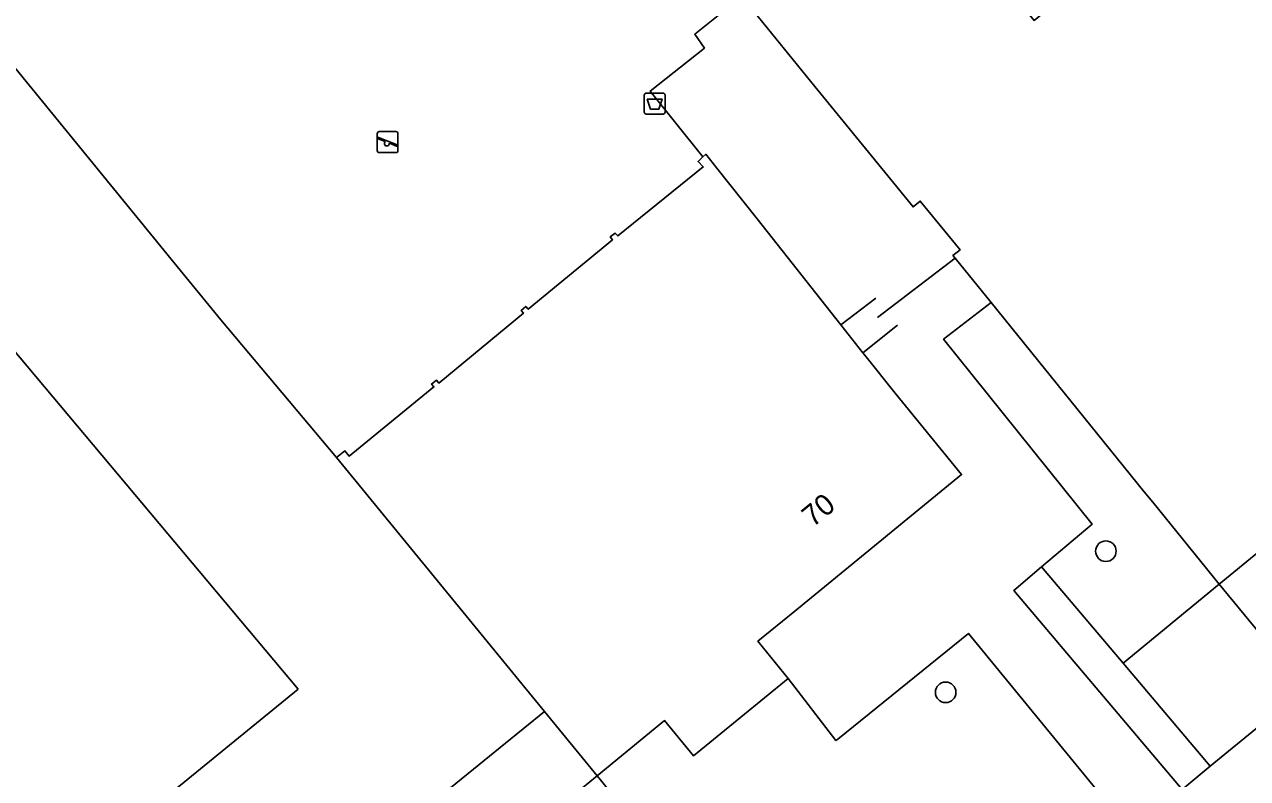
# Model space of a CAD drawing. Extents: x 162074 to 163034, y 381824 to 382557.
# Drawn here: x 162552.1 to 162610.3, y 381921.2 to 381957.1 of the extents above; entities that cross this region are included whole.
import ezdxf

# ---------------------------------------------------------------- set-up
doc = ezdxf.new("R2010")
doc.units = 0
for name, color, linetype in [('IMGEO_Afvalbak', 7, 'Continuous'), ('IMGEO_Boom', 7, 'Continuous'), ('IMGEO_Groenvoorziening', 7, 'Continuous'), ('IMGEO_Hek', 7, 'Continuous'), ('IMGEO_Pand', 7, 'Continuous'), ('IMGEO_Pand_nummerreeks', 7, 'Continuous'), ('IMGEO_Rijbaan_lokaal_open', 7, 'Continuous'), ('IMGEO_Rijbaan_regionaal_gesloten', 7, 'Continuous'), ('IMGEO_Speelvoorziening', 7, 'Continuous'), ('IMGEO_Voetpad_open', 7, 'Continuous')]:
    doc.layers.add(name, color=color, linetype=linetype)

msp = doc.modelspace()

# ---------------------------------------------------------------- linework, layer by layer
at = {"layer": 'IMGEO_Afvalbak'}
for p, q in [((162581.607, 381952.905), (162581.607, 381953.705)), ((162581.607, 381953.705), (162581.607, 381952.905)), ((162581.707, 381953.805), (162582.497, 381953.805)), ((162582.497, 381953.805), (162581.707, 381953.805)), ((162582.597, 381953.705), (162582.597, 381952.905)), ((162582.597, 381952.905), (162582.597, 381953.705)), ((162582.497, 381952.805), (162581.707, 381952.805)), ((162581.707, 381952.805), (162582.497, 381952.805))]:
    msp.add_line(p, q, dxfattribs=at)
msp.add_lwpolyline([(162581.75, 381953.519), (162582.454, 381953.519), (162582.305, 381953.049), (162581.899, 381953.049), (162581.75, 381953.519)], dxfattribs=at)
for centre, start, end in [((162581.707, 381953.705), 90, 180), ((162581.707, 381953.705), 90, 180), ((162582.497, 381953.705), 0, 90), ((162582.497, 381953.705), 360, 90), ((162581.707, 381952.905), 180, 270), ((162581.707, 381952.905), 180, 270), ((162582.497, 381952.905), 270, 0), ((162582.497, 381952.905), 270, 0)]:
    msp.add_arc(centre, 0.1, start, end, dxfattribs=at)
at = {"layer": 'IMGEO_Boom'}
for centre in [(162603.558, 381932.03), (162595.937, 381925.32)]:
    msp.add_circle(centre, 0.489, dxfattribs=at)
at = {"layer": 'IMGEO_Groenvoorziening'}
for points in [[(162604.374, 381926.708), (162600.502, 381931.282)], [(162608.939, 381930.467), (162604.374, 381926.708)], [(162608.939, 381930.467), (162613.031, 381925.508)], [(162608.52, 381921.81), (162604.374, 381926.708)], [(162579.358, 381921.35), (162583.171, 381916.7), (162590.856, 381907.327)]]:
    msp.add_lwpolyline(points, dxfattribs=at)
at = {"layer": 'IMGEO_Hek'}
for points in [[(162592.7, 381943.146), (162596.393, 381945.952)], [(162590.953, 381942.794), (162592.612, 381944.061)], [(162592.007, 381941.465), (162593.649, 381942.77)]]:
    msp.add_lwpolyline(points, dxfattribs=at)
at = {"layer": 'IMGEO_Pand'}
for points in [[(162580.989, 381965.07), (162582.996, 381966.707), (162590.131, 381957.956), (162595.778, 381962.577), (162600.14, 381957.261), (162625.783, 381978.273), (162640.017, 381960.503), (162633.898, 381955.497), (162633.564, 381955.907), (162630.873, 381953.706), (162633.469, 381950.533), (162608.939, 381930.467)], [(162598.107, 381943.844), (162596.393, 381945.952), (162596.286, 381946.083), (162596.627, 381946.361), (162594.733, 381948.676), (162594.392, 381948.398), (162589.722, 381954.124), (162586.627, 381957.92), (162581.57, 381964.121), (162580.873, 381964.976), (162580.989, 381965.07)], [(162548.165, 381953.339), (162551.085, 381955.732), (162551.227, 381955.558), (162559.253, 381945.742), (162561.474, 381943.025), (162566.975, 381936.477)], [(162566.975, 381936.477), (162567.37, 381936.798), (162567.572, 381936.549), (162571.599, 381939.84), (162571.491, 381939.972), (162571.725, 381940.162), (162571.838, 381940.019), (162575.86, 381943.339), (162575.746, 381943.465), (162575.969, 381943.667), (162576.085, 381943.534), (162580.093, 381946.834), (162579.987, 381946.967), (162580.22, 381947.152), (162580.344, 381947.013), (162584.407, 381950.296), (162584.167, 381950.55), (162584.397, 381950.771)], [(162584.397, 381950.771), (162584.532, 381950.895), (162585.058, 381950.231), (162586.967, 381947.822), (162590.953, 381942.794), (162592.007, 381941.465), (162592.161, 381941.27), (162593.53, 381939.543), (162596.696, 381935.673), (162588.759, 381929.179), (162587.009, 381927.748), (162588.456, 381925.978)], [(162598.107, 381943.844), (162605.386, 381934.855), (162605.792, 381934.353), (162608.939, 381930.467)], [(162565.141, 381925.467), (162548.187, 381911.662), (162535.815, 381926.855), (162551.463, 381939.598), (162550.445, 381940.847), (162551.517, 381941.719), (162565.141, 381925.467)], [(162576.856, 381924.407), (162566.975, 381936.477)], [(162588.456, 381925.978), (162583.953, 381922.295), (162582.574, 381923.981), (162579.358, 381921.35)], [(162574.906, 381913.476), (162571.749, 381917.353), (162570.041, 381919.451), (162571.599, 381920.72), (162571.89, 381920.363), (162576.856, 381924.407)], [(162576.856, 381924.407), (162579.358, 381921.35)]]:
    msp.add_lwpolyline(points, dxfattribs=at)
at = {"layer": 'IMGEO_Rijbaan_lokaal_open'}
msp.add_lwpolyline([(162579.358, 381921.35), (162578.487, 381920.638)], dxfattribs=at)
at = {"layer": 'IMGEO_Rijbaan_regionaal_gesloten'}
msp.add_arc((167033.423, 376567.715), 6927.186, 129.0651232, 129.6890786, dxfattribs=at)
at = {"layer": 'IMGEO_Speelvoorziening'}
for p, q in [((162568.904, 381951.074), (162568.904, 381951.874)), ((162568.904, 381951.874), (162568.904, 381951.074)), ((162569.004, 381951.974), (162569.794, 381951.974)), ((162569.794, 381951.974), (162569.004, 381951.974)), ((162569.894, 381951.874), (162569.894, 381951.074)), ((162569.894, 381951.074), (162569.894, 381951.874)), ((162569.287, 381951.502), (162568.948, 381951.639)), ((162568.973, 381951.699), (162569.849, 381951.346)), ((162569.825, 381951.286), (162569.485, 381951.423)), ((162569.794, 381950.974), (162569.004, 381950.974)), ((162569.004, 381950.974), (162569.794, 381950.974))]:
    msp.add_line(p, q, dxfattribs=at)
for centre, radius, start, end in [((162569.004, 381951.874), 0.1, 90, 180), ((162569.004, 381951.874), 0.1, 90, 180), ((162569.794, 381951.874), 0.1, 0, 90), ((162569.794, 381951.874), 0.1, 360, 90), ((162568.961, 381951.669), 0.0327, 68.07798, 248.07798), ((162569.366, 381951.412), 0.12, 130.99278, 5.16318), ((162569.837, 381951.316), 0.0327, 248.07798, 68.07798), ((162569.004, 381951.074), 0.1, 180, 270), ((162569.004, 381951.074), 0.1, 180, 270), ((162569.794, 381951.074), 0.1, 270, 0), ((162569.794, 381951.074), 0.1, 270, 0)]:
    msp.add_arc(centre, radius, start, end, dxfattribs=at)
at = {"layer": 'IMGEO_Voetpad_open'}
for points in [[(162584.397, 381950.771), (162581.893, 381953.902), (162584.469, 381955.945), (162584.006, 381956.601), (162585.51, 381957.818), (162579.335, 381965.469), (162579.619, 381965.685), (162579.531, 381965.793), (162580.073, 381966.206), (162580.989, 381965.07)], [(162600.502, 381931.282), (162602.898, 381933.31), (162595.841, 381942.105), (162598.107, 381943.844)], [(162607.178, 381920.71), (162599.178, 381930.161), (162600.502, 381931.282)], [(162588.456, 381925.978), (162590.717, 381923.029), (162590.804, 381923.099), (162597.019, 381928.123), (162604.738, 381918.709)], [(162613.031, 381925.508), (162608.52, 381921.81)], [(162608.52, 381921.81), (162607.178, 381920.71)]]:
    msp.add_lwpolyline(points, dxfattribs=at)

# ---------------------------------------------------------------- texts
at = {"layer": 'IMGEO_Pand_nummerreeks'}
msp.add_text('70', height=1, rotation=39.28683, dxfattribs=at).set_placement((162589.62, 381933.139))

doc.saveas('drawing.dxf')
